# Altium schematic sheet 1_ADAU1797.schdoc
size 848 x 601 mm; Symbol: Drawing-Symbol_A4; Device: Drawing-Symbol_A4; @Project Name: Slowpoke; @Page Count: 7; @Update Date: 2025-12-15; @Create Date: 2025-12-13; @Schematic Name: Slowpoke_Sch; @Page No: 1; @Page Name: ADAU1797; Company: Analog Devices, Inc.; Version: V1.0; Page Size: A0; Drawn: Bruce Tsao; @Create Time: 14:28:29; @Update Time: 16:38:32; Width: 3304; Height: 2338; Region Start: 1; X Region Count: 6; Y Region Count: 4; Blade Width: 10; Title Block Position: 3; @Board Name: Slowpoke
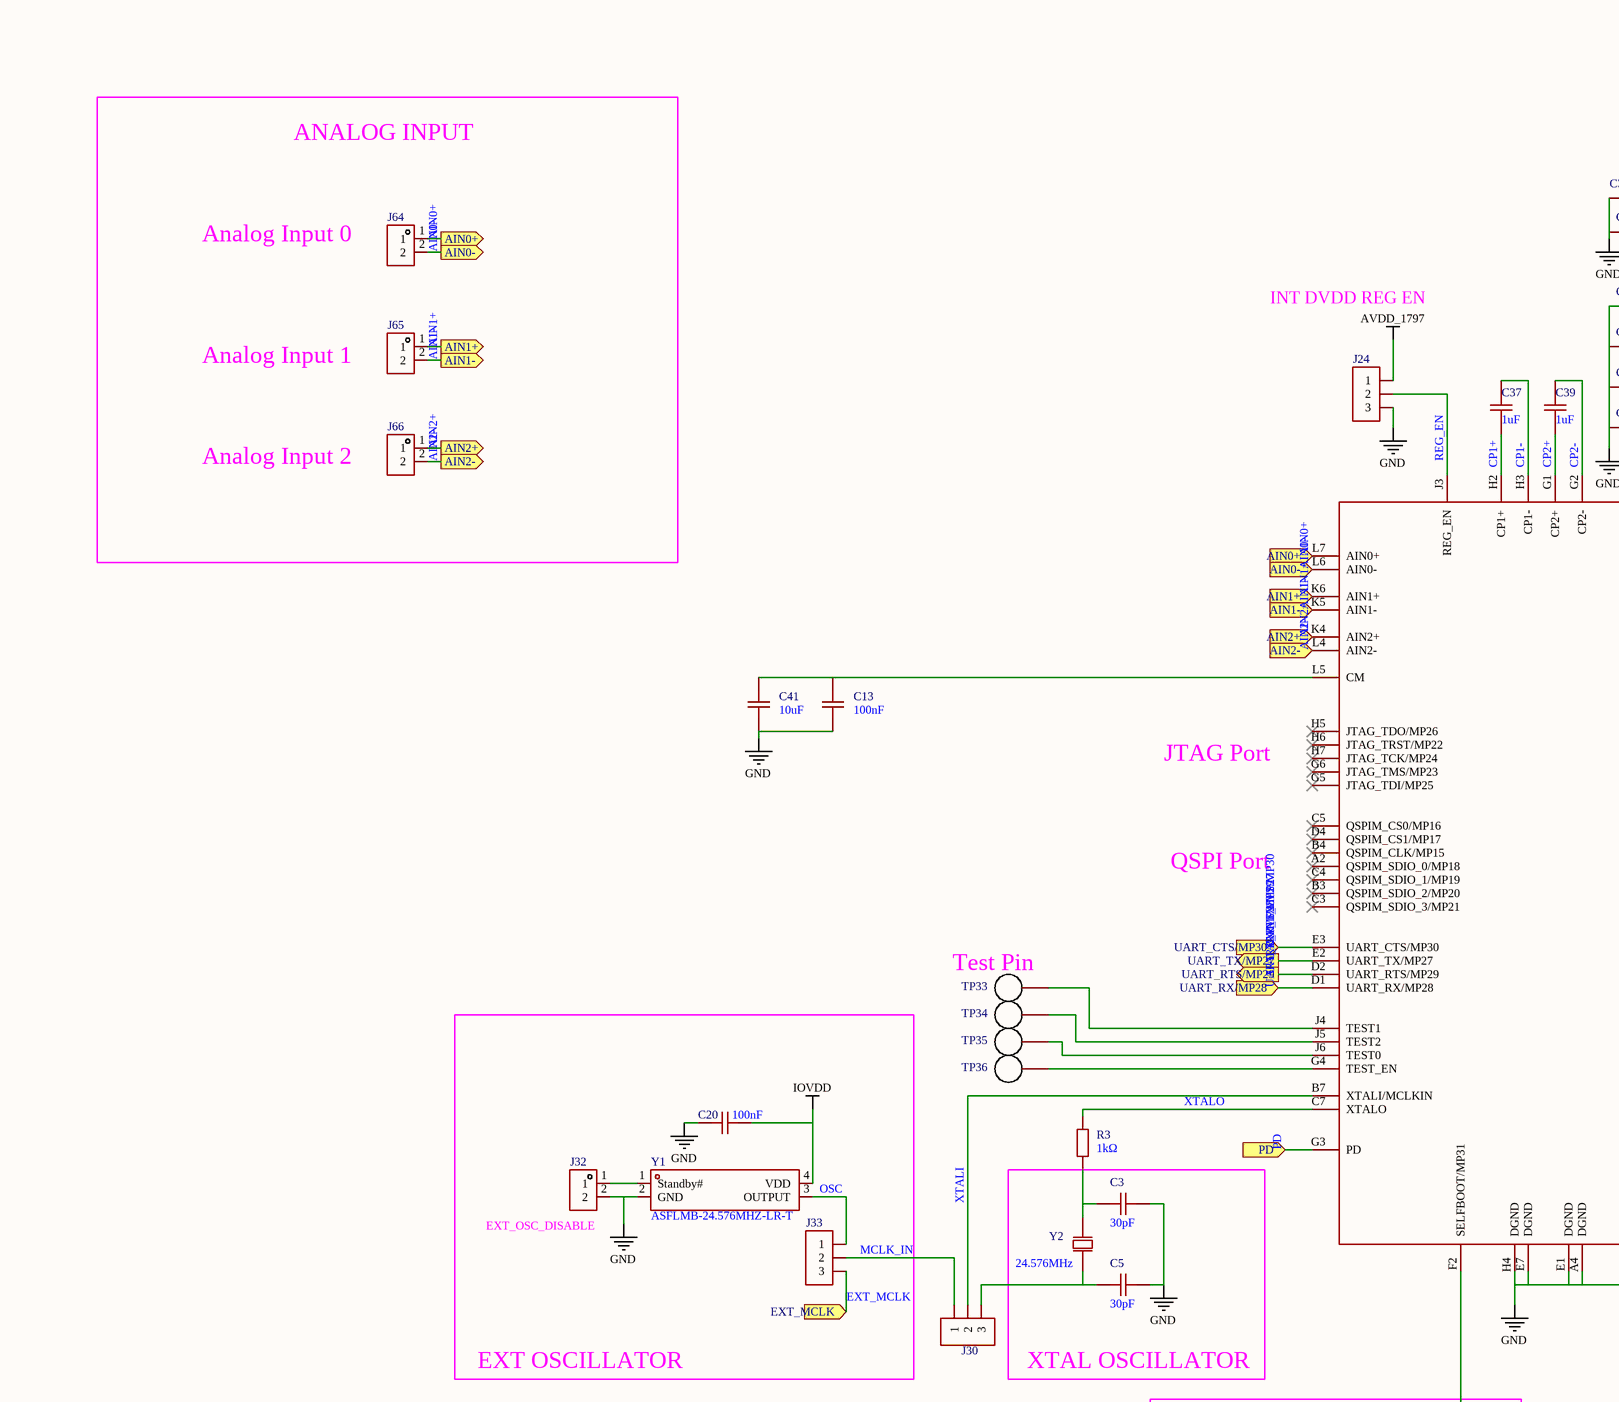
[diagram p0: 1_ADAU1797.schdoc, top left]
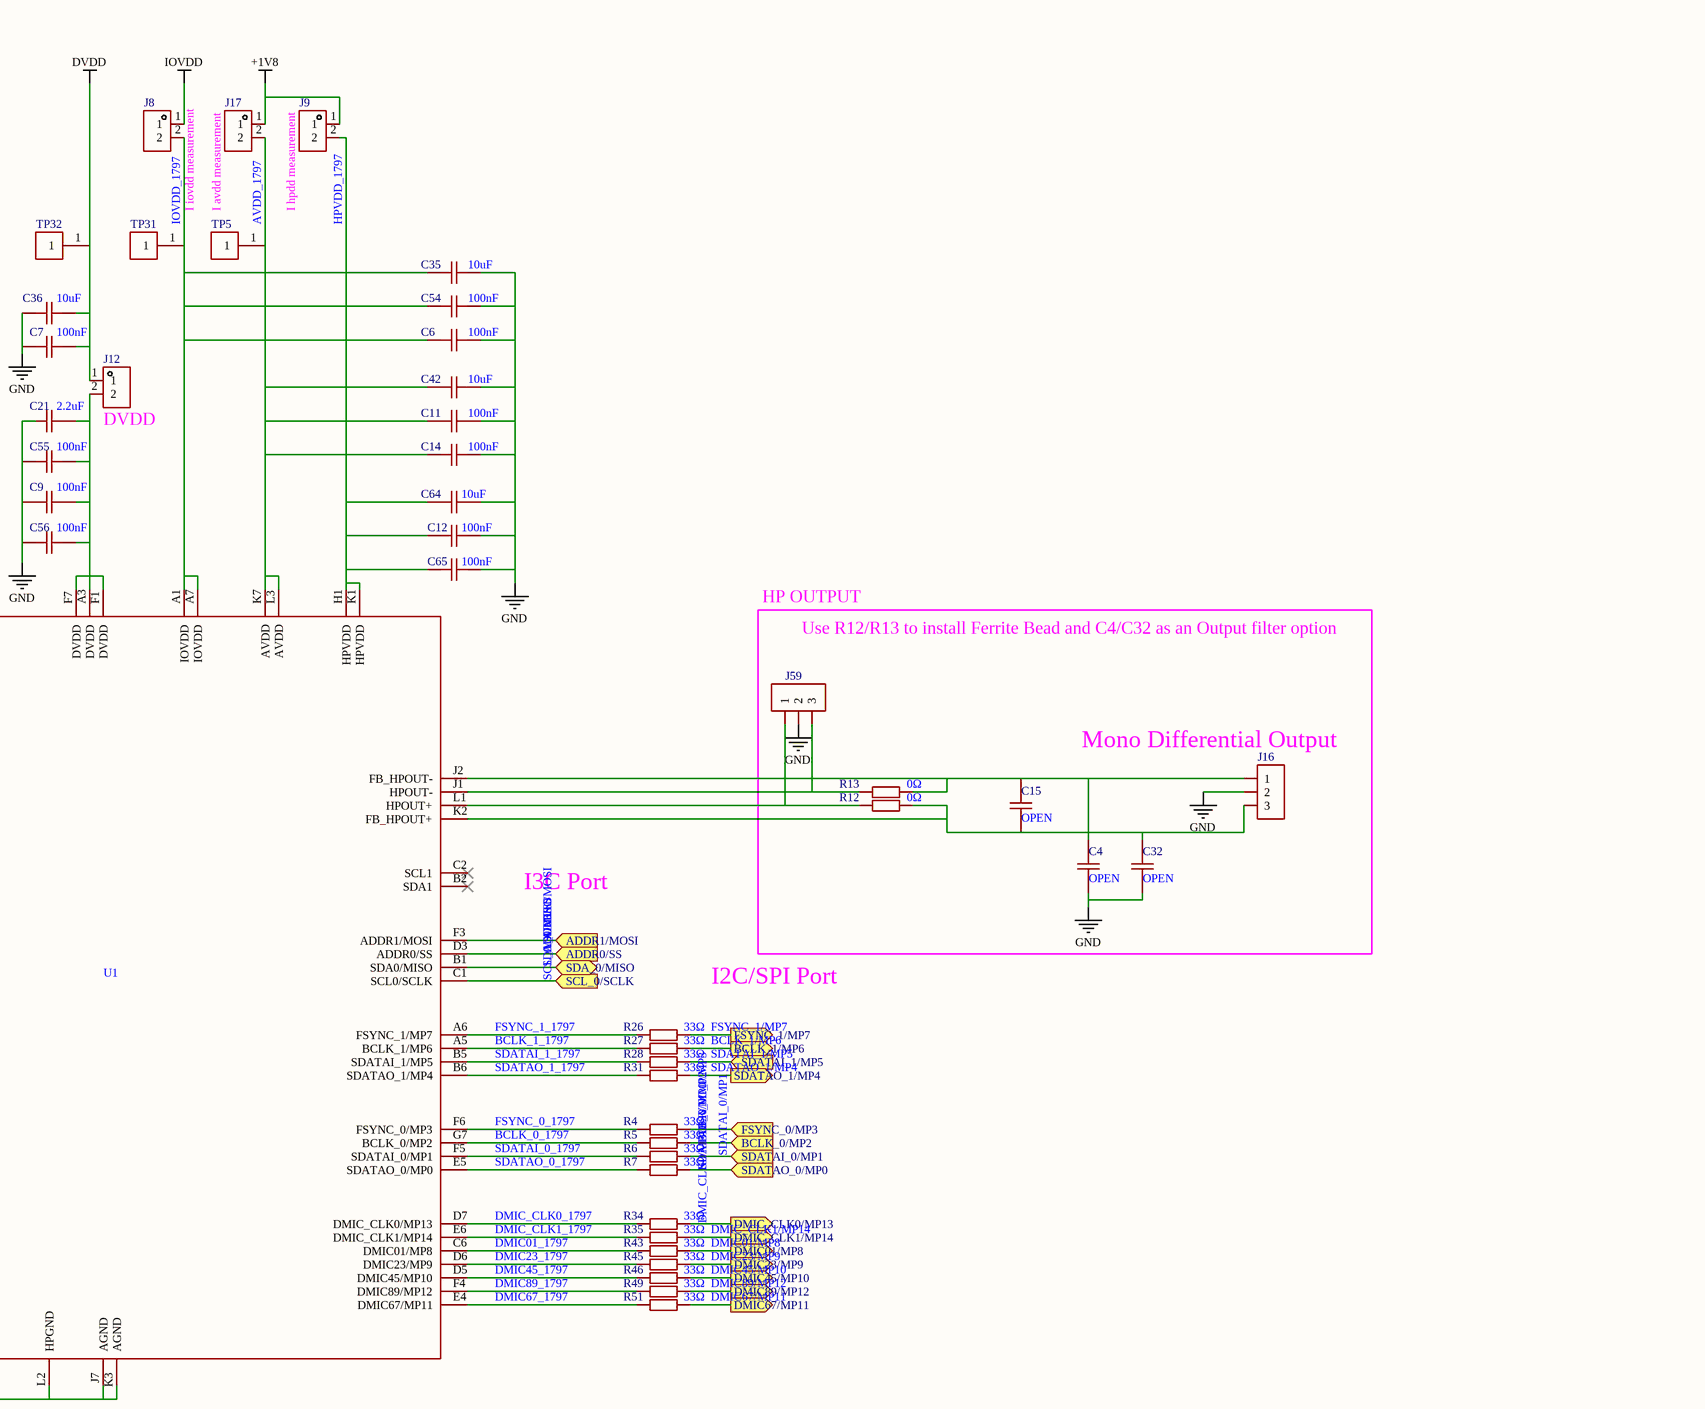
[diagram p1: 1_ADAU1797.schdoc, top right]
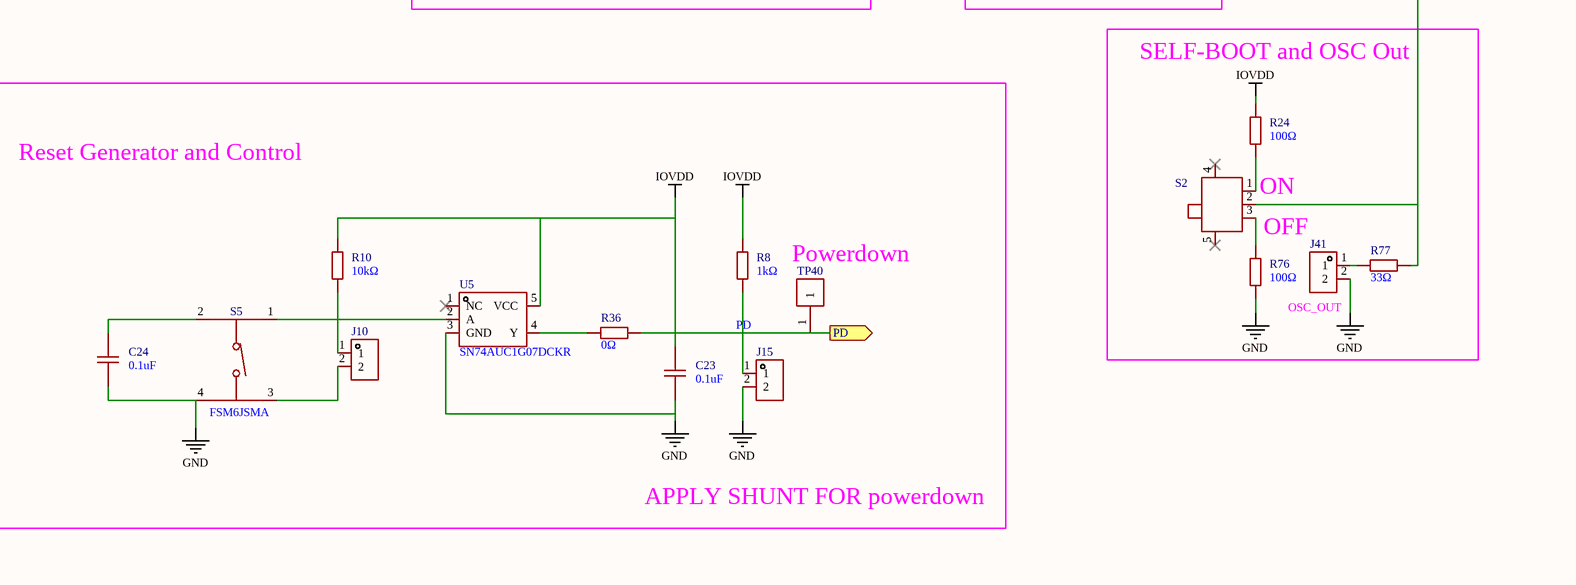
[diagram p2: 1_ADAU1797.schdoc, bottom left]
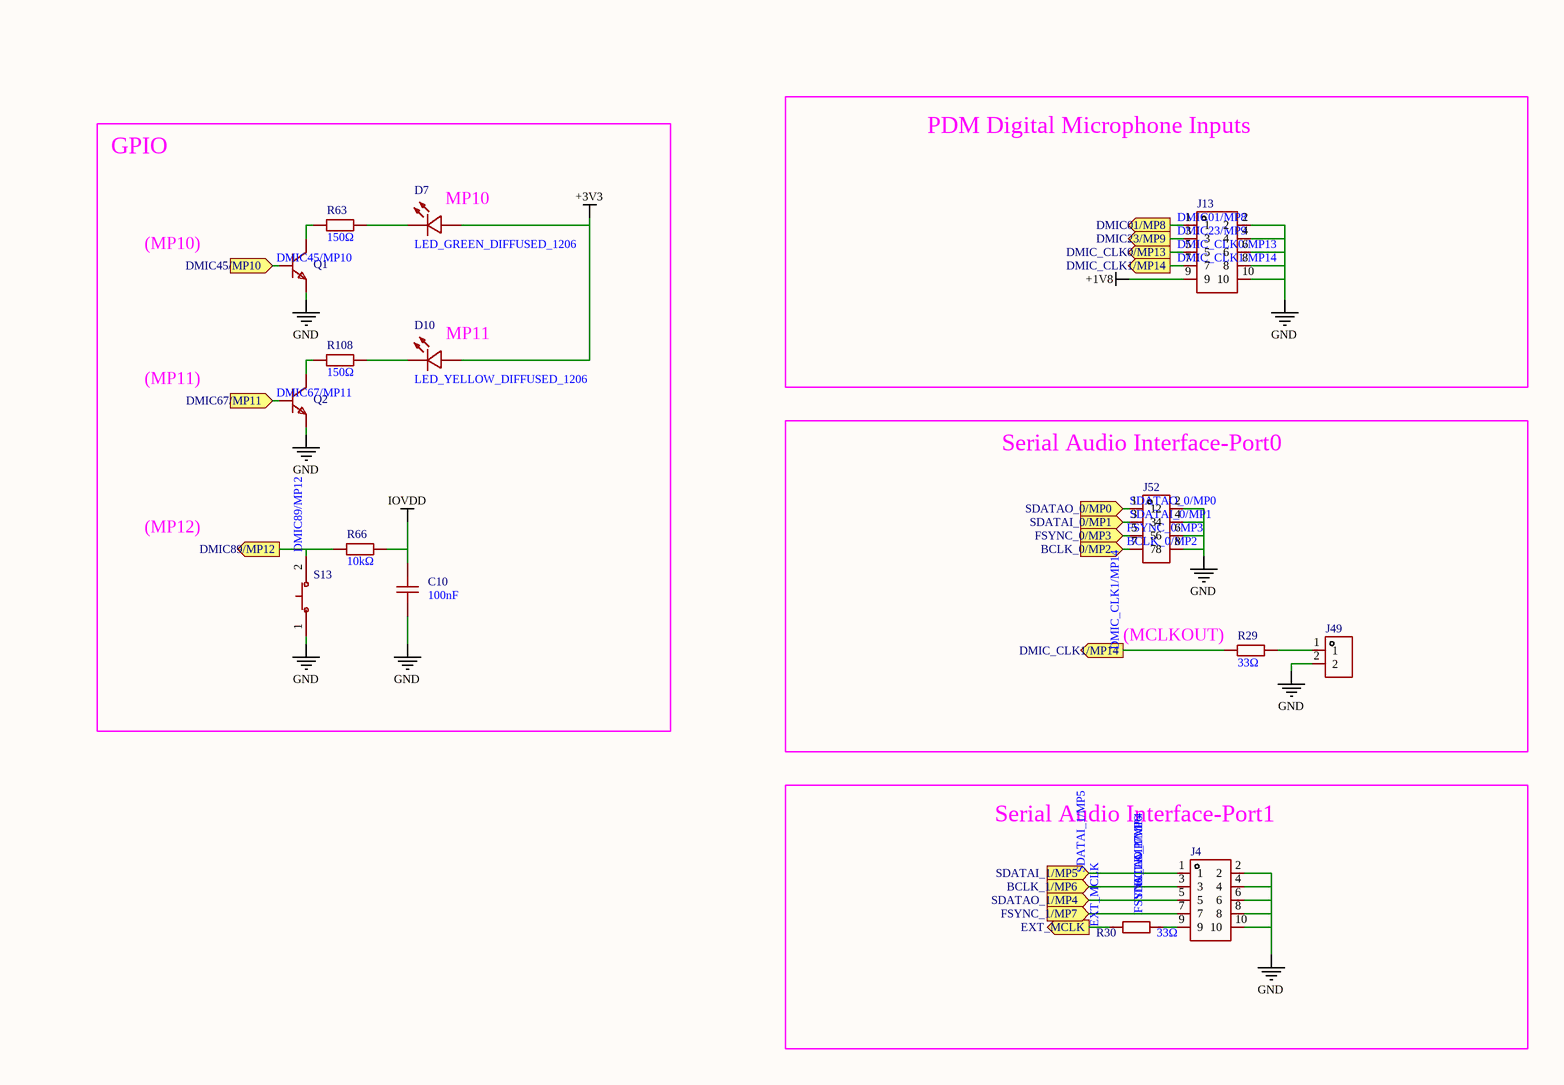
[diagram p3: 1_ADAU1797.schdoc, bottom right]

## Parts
C3  30pF  [C0201]
C4  OPEN  [C0603]
C5  30pF  [C0201]
C6  100nF  [C0402]
C7  100nF  [C0402]
C9  100nF  [C0402]
C10  100nF  [C0402]
C11  100nF  [C0402]
C12  100nF  [C0402]
C13  100nF  [C0402]
C14  100nF  [C0402]
C15  OPEN  [C0603]
C20  100nF  [C0402]
C21  2.2uF  [C0402]
C23  0.1uF  [C0402]
C24  0.1uF  [C0402]
C32  OPEN  [C0603]
C35  10uF  [C0402]
C36  10uF  [C0402]
C37  1uF  [C0402]
C39  1uF  [C0402]
C41  10uF  [C0402]
C42  10uF  [C0402]
C54  100nF  [C0402]
C55  100nF  [C0402]
C56  100nF  [C0402]
C64  10uF  [C0402]
C65  100nF  [C0402]
D7  LED_GREEN_DIFFUSED_1206  [LED1206-RD]
D10  LED_YELLOW_DIFFUSED_1206  [LED1206-RD]
J4  PZ254V-12-10P  [HDR-TH_10P-P2.54-V-M-R2-C5-S2.54]  (value not drawn)
J8  PZ254V-11-02P  [HDR-TH_2P-P2.54-V-M]  (value not drawn)
J9  PZ254V-11-02P  [HDR-TH_2P-P2.54-V-M]  (value not drawn)
J10  PZ254V-11-02P  [HDR-TH_2P-P2.54-V-M]  (value not drawn)
J12  PZ254V-11-02P  [HDR-TH_2P-P2.54-V-M]  (value not drawn)
J13  PZ254V-12-10P  [HDR-TH_10P-P2.54-V-M-R2-C5-S2.54]  (value not drawn)
J15  PZ254V-11-02P  [HDR-TH_2P-P2.54-V-M]  (value not drawn)
J16  2.54-1*3P针  [HDR-TH_3P-P2.54-V-M-1]  (value not drawn)
J17  PZ254V-11-02P  [HDR-TH_2P-P2.54-V-M]  (value not drawn)
J24  2.54-1*3P针  [HDR-TH_3P-P2.54-V-M-1]  (value not drawn)
J30  2.54-1*3P针  [HDR-TH_3P-P2.54-V-M-1]  (value not drawn)
J32  PZ254V-11-02P  [HDR-TH_2P-P2.54-V-M]  (value not drawn)
J33  2.54-1*3P针  [HDR-TH_3P-P2.54-V-M-1]  (value not drawn)
J41  PZ254V-11-02P  [HDR-TH_2P-P2.54-V-M]  (value not drawn)
J49  PZ254V-11-02P  [HDR-TH_2P-P2.54-V-M]  (value not drawn)
J52  PZ254V-12-8P  [HDR-TH_8P-P2.54-V-M-R2-C4-S2.54]  (value not drawn)
J59  2.54-1*3P针  [HDR-TH_3P-P2.54-V-M-1]  (value not drawn)
J64  PZ254V-11-02P  [HDR-TH_2P-P2.54-V-M]  (value not drawn)
J65  PZ254V-11-02P  [HDR-TH_2P-P2.54-V-M]  (value not drawn)
J66  PZ254V-11-02P  [HDR-TH_2P-P2.54-V-M]  (value not drawn)
Q1  DTC114YET1G  [SC-75-3_L1.6-W0.8-P1.00-LS1.7-BR]  (value not drawn)
Q2  DTC114YET1G  [SC-75-3_L1.6-W0.8-P1.00-LS1.7-BR]  (value not drawn)
R3  1kΩ  [R0201]
R4  33Ω  [R0201]
R5  33Ω  [R0201]
R6  33Ω  [R0201]
R7  33Ω  [R0201]
R8  1kΩ  [R0201]
R10  10kΩ  [R0201]
R12  0Ω  [R0603]
R13  0Ω  [R0603]
R24  100Ω  [R0201]
R26  33Ω  [R0201]
R27  33Ω  [R0201]
R28  33Ω  [R0201]
R29  33Ω  [R0201]
R30  33Ω  [R0201]
R31  33Ω  [R0201]
R34  33Ω  [R0201]
R35  33Ω  [R0201]
R36  0Ω  [R0402]
R43  33Ω  [R0201]
R45  33Ω  [R0201]
R46  33Ω  [R0201]
R49  33Ω  [R0201]
R51  33Ω  [R0201]
R63  150Ω  [R0805]
R66  10kΩ  [R0201]
R76  100Ω  [R0201]
R77  33Ω  [R0201]
R108  150Ω  [R0805]
S2  SS12D07VG4 087  [SW-TH_SS12D07VG4]  (value not drawn)
S5  FSM6JSMA  [SW-SMD_4P-L6.0-W6.0-P4.50-LS10.0-BL]
S13  TS3643TP  [KEY-SMD_L6.0-W3.5-LS8.4]  (value not drawn)
TP5  RH-5000  [TEST-TH_BD2.54-P1.4_RED]  (value not drawn)
TP31  RH-5000  [TEST-TH_BD2.54-P1.4_RED]  (value not drawn)
TP32  RH-5000  [TEST-TH_BD2.54-P1.4_RED]  (value not drawn)
TP33  RH-5002  [TESTPOINT-TH_BD2.5-D1.2_RH-5002]  (value not drawn)
TP34  RH-5002  [TESTPOINT-TH_BD2.5-D1.2_RH-5002]  (value not drawn)
TP35  RH-5002  [TESTPOINT-TH_BD2.5-D1.2_RH-5002]  (value not drawn)
TP36  RH-5002  [TESTPOINT-TH_BD2.5-D1.2_RH-5002]  (value not drawn)
TP40  RH-5000  [TEST-TH_BD2.54-P1.4_RED]  (value not drawn)
U1  (no value)  [ADAU1797_WLCSP_CB-77-1]
U5  SN74AUC1G07DCKR  [SC-70-5_L2.0-W1.3-P0.65-LS2.1-BR]
Y1  ASFLMB-24.576MHZ-LR-T  [OSC-SMD_4P-L5.0-W3.2-BL_ASFLMB]
Y2  24.576MHz  [HC-49US_L11.5-W4.5-P4.88]

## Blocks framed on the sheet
Mono Differential Output: C4 C15 C32 J16 J59 R12 R13
EXT OSCILLATOR: C20 J32 J33 Y1
XTAL OSCILLATOR: C3 C5 Y2
GPIO: C10 D7 D10 Q1 Q2 R63 R66 R108 S13
PDM Digital Microphone Inputs: J13
Serial Audio Interface-Port0: J49 J52 R29
Serial Audio Interface-Port1: J4 R30

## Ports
ADDR0/SS (in), ADDR1/MOSI (in), AIN0+ (in), AIN0+ (out), AIN0- (in), AIN0- (out), AIN1+ (in), AIN1+ (out), AIN1- (in), AIN1- (out), AIN2+ (in), AIN2+ (out), AIN2- (in), AIN2- (out), BCLK_0/MP2 (in), BCLK_1/MP6 (in), BCLK_1/MP6 (out), DMIC01/MP8 (out), DMIC23/MP9 (out), DMIC45/MP10 (in), DMIC45/MP10 (out), DMIC67/MP11 (in), DMIC67/MP11 (out), DMIC89/MP12 (out), DMIC_CLK0/MP13 (out), DMIC_CLK1/MP14 (out), EXT_MCLK (in), EXT_MCLK (out), FSYNC_0/MP3 (in), FSYNC_1/MP7 (in), FSYNC_1/MP7 (out), PD (in), PD (out), SCL_0/SCLK (in), SDA_0/MISO (bidir), SDATAI_0/MP1 (in), SDATAI_1/MP5 (in), SDATAO_0/MP0 (in), SDATAO_1/MP4 (in), SDATAO_1/MP4 (out), UART_CTS/MP30 (in), UART_RTS/MP29 (out), UART_RX/MP28 (in), UART_TX/MP27 (out)

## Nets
+1V8: J9.1 J13.9 J17.1
+3V3: D7.2(A) D10.2(A)
AVDD_1797: C11.2 C14.2 C42.2 J17.2 J24.1 TP5.1 U1.K7(AVDD) U1.L3(AVDD)
DVDD: C7.1 C36.1 J12.1 TP32.1
GND: C3.1 C4.1 C5.1 C6.1 C7.2 C9.2 C10.2 C11.1 C12.1 C13.2 C14.1 C20.2 C21.2 C23.2 C24.1 C32.1 C35.1 C36.2 C41.2 C42.1 C54.1 C55.2 C56.2 C64.1 C65.1 J4.2 J4.4 J4.6 J4.8 J4.10 J13.2 J13.4 J13.6 J13.8 J13.10 J15.2 J16.2 J24.3 J32.2 J41.2 J49.2 J52.2 J52.4 J52.6 J52.8 J59.2 Q1.2(E) Q2.2(E) R76.1 S5.4 S13.1 U1.A4(DGND) U1.E1(DGND) U1.E7(DGND) U1.H4(DGND) U1.J7(AGND) U1.K3(AGND) U1.L2(HPGND) U5.3(GND) Y1.2(GND)
IOVDD: C10.1 C20.1 C23.1 J8.1 R8.2 R10.2 R24.2 R66.1 U5.5(VCC) Y1.4(VDD)
ADDR0/SS: U1.D3(ADDR0/SS) ; port ADDR0/SS
ADDR1/MOSI: U1.F3(ADDR1/MOSI) ; port ADDR1/MOSI
AIN0+: J64.1 U1.L7(AIN0+) ; port AIN0+
AIN0-: J64.2 U1.L6(AIN0-) ; port AIN0-
AIN1+: J65.1 U1.K6(AIN1+) ; port AIN1+
AIN1-: J65.2 U1.K5(AIN1-) ; port AIN1-
AIN2+: J66.1 U1.K4(AIN2+) ; port AIN2+
AIN2-: J66.2 U1.L4(AIN2-) ; port AIN2-
BCLK_0/MP2: J52.7 R5.2 ; port BCLK_0/MP2
BCLK_0_1797: R5.1 U1.G7(BCLK_0/MP2)
BCLK_1/MP6: J4.3 R27.2 ; port BCLK_1/MP6
BCLK_1_1797: R27.1 U1.A5(BCLK_1/MP6)
CP1+: C37.1 U1.H2(CP1+)
CP1-: C37.2 U1.H3(CP1-)
CP2+: C39.1 U1.G1(CP2+)
CP2-: C39.2 U1.G2(CP2-)
DMIC01/MP8: J13.1 R43.2 ; port DMIC01/MP8
DMIC01_1797: R43.1 U1.C6(DMIC01/MP8)
DMIC23/MP9: J13.3 R45.2 ; port DMIC23/MP9
DMIC23_1797: R45.1 U1.D6(DMIC23/MP9)
DMIC45/MP10: Q1.1(B) R46.2 ; port DMIC45/MP10
DMIC45_1797: R46.1 U1.D5(DMIC45/MP10)
DMIC67/MP11: Q2.1(B) R51.2 ; port DMIC67/MP11
DMIC67_1797: R51.1 U1.E4(DMIC67/MP11)
DMIC89/MP12: R49.2 R66.2 S13.2 ; port DMIC89/MP12
DMIC89_1797: R49.1 U1.F4(DMIC89/MP12)
DMIC_CLK0/MP13: J13.5 R34.2 ; port DMIC_CLK0/MP13
DMIC_CLK0_1797: R34.1 U1.D7(DMIC_CLK0/MP13)
DMIC_CLK1/MP14: J13.7 R29.1 R35.2 ; port DMIC_CLK1/MP14
DMIC_CLK1_1797: R35.1 U1.E6(DMIC_CLK1/MP14)
EXT_MCLK: J33.3 R30.1 ; port EXT_MCLK
FSYNC_0/MP3: J52.5 R4.2 ; port FSYNC_0/MP3
FSYNC_0_1797: R4.1 U1.F6(FSYNC_0/MP3)
FSYNC_1/MP7: J4.7 R26.2 ; port FSYNC_1/MP7
FSYNC_1_1797: R26.1 U1.A6(FSYNC_1/MP7)
HPVDD_1797: C12.2 C64.2 C65.2 J9.2 U1.H1(HPVDD) U1.K1(HPVDD)
IOVDD_1797: C6.2 C35.2 C54.2 J8.2 TP31.1 U1.A1(IOVDD) U1.A7(IOVDD)
MCLK_IN: J30.1 J33.2
OSC: J33.1 Y1.3(OUTPUT)
PD: J15.1 R8.1 R36.2 TP40.1 U1.G3(PD) ; port PD
REG_EN: J24.2 U1.J3(REG_EN)
SCL_0/SCLK: U1.C1(SCL0/SCLK) ; port SCL_0/SCLK
SDA_0/MISO: U1.B1(SDA0/MISO) ; port SDA_0/MISO
SDATAI_0/MP1: J52.3 R6.2 ; port SDATAI_0/MP1
SDATAI_0_1797: R6.1 U1.F5(SDATAI_0/MP1)
SDATAI_1/MP5: J4.1 R28.2 ; port SDATAI_1/MP5
SDATAI_1_1797: R28.1 U1.B5(SDATAI_1/MP5)
SDATAO_0/MP0: J52.1 R7.2 ; port SDATAO_0/MP0
SDATAO_0_1797: R7.1 U1.E5(SDATAO_0/MP0)
SDATAO_1/MP4: J4.5 R31.2 ; port SDATAO_1/MP4
SDATAO_1_1797: R31.1 U1.B6(SDATAO_1/MP4)
UART_CTS/MP30: U1.E3(UART_CTS/MP30) ; port UART_CTS/MP30
UART_RTS/MP29: U1.D2(UART_RTS/MP29) ; port UART_RTS/MP29
UART_RX/MP28: U1.D1(UART_RX/MP28) ; port UART_RX/MP28
UART_TX/MP27: U1.E2(UART_TX/MP27) ; port UART_TX/MP27
XTALI: J30.2 U1.B7(XTALI/MCLKIN)
XTALO: R3.2 U1.C7(XTALO)
NetC3_2: C3.2 R3.1 Y2.2(OSC2)
NetC4_2: C4.2 C15.2 J16.1 R13.2 U1.J2(FB_HPOUT-)
NetC5_2: C5.2 J30.3 Y2.1(OSC1)
NetC9_1: C9.1 C21.1 C55.1 C56.1 J12.2 U1.A3(DVDD) U1.F1(DVDD) U1.F7(DVDD)
NetC13_1: C13.1 C41.1 U1.L5(CM)
NetC15_1: C15.1 C32.2 J16.3 R12.2 U1.K2(FB_HPOUT+)
NetC24_2: C24.2 S5.2
NetD7_1: D7.1(K) R63.1
NetD10_1: D10.1(K) R108.1
NetJ4_9: J4.9 R30.2
NetJ10_1: J10.1 R10.1 S5.1 U5.2(A)
NetJ10_2: J10.2 S5.3
NetJ32_1: J32.1 Y1.1(Standby#)
NetJ41_1: J41.1 R77.1
NetJ49_1: J49.1 R29.2
NetJ59_1: J59.1 R12.1 U1.L1(HPOUT+)
NetJ59_3: J59.3 R13.1 U1.J1(HPOUT-)
NetQ1_3: Q1.3(C) R63.2
NetQ2_3: Q2.3(C) R108.2
NetR24_1: R24.1 S2.1
NetR36_1: R36.1 U5.4(Y)
NetR76_2: R76.2 S2.3
NetR77_2: R77.2 S2.2 U1.F2(SELFBOOT/MP31)
NetTP33_1: TP33.1 U1.J4(TEST1)
NetTP34_1: TP34.1 U1.J5(TEST2)
NetTP35_1: TP35.1 U1.J6(TEST0)
NetTP36_1: TP36.1 U1.G4(TEST_EN)

Not connected (* = marked no-connect by the designer): S2 4* 5*; U1 A2(QSPIM_SDIO_0/MP18)* B2(SDA1)* B3(QSPIM_SDIO_2/MP20)* B4(QSPIM_CLK/MP15)* C2(SCL1)* C3(QSPIM_SDIO_3/MP21)* C4(QSPIM_SDIO_1/MP19)* C5(QSPIM_CS0/MP16)* D4(QSPIM_CS1/MP17)* G5(JTAG_TDI/MP25)* G6(JTAG_TMS/MP23)* H5(JTAG_TDO/MP26)* H6(JTAG_TRST/MP22)* H7(JTAG_TCK/MP24)*; U5 1(NC)*

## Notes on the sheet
- (near J8) I iovdd measurement
- I avdd measurement
- I hpdd measurement
- ANALOG INPUT
- Analog Input 0
- INT DVDD REG EN
- (near J12) DVDD
- Analog Input 1
- Analog Input 2
- HP OUTPUT
- Use R12/R13 to install Ferrite Bead and C4/C32 as an Output filter option
- JTAG Port
- I3C Port
- QSPI Port
- I2C/SPI Port
- (near TP33) Test Pin
- (near J32) EXT_OSC_DISABLE
- SELF-BOOT and OSC Out
- Reset Generator and Control
- (MP10)
- (near D7) MP10
- ON
- OFF
- Powerdown
- (MP11)
- (near D10) MP11
- (near J41) OSC_OUT
- (MP12)
- APPLY SHUNT FOR powerdown
- (near R29) (MCLKOUT)

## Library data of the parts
C3 C5 = GRM0335C1H300GA01D: Manufacturer: muRata(村田); Add into BOM: yes; Tolerance: ±2%
C4 C15 C32 = CGA0603X5R105K500JT: Manufacturer: HRE(芯声); Symbol: 0402X7R104K500NT; Add into BOM: yes; Tolerance: ±10%; Voltage Rating: 50V; Temperature Coefficient: X5R
C6 C7 C9-C14 C20 C21 C35 C36 C41 C42 C54-C56 C64 C65 = FCC0402B104K160AT: Manufacturer: FOJAN(富捷); Symbol: C1005X5R225MCT; Add into BOM: yes; Tolerance: ±10%; Voltage Rating: 16V; Temperature Coefficient: X7R
C23 C24 = GRM155R71C104KA88D: Manufacturer: muRata(村田); Add into BOM: yes; Tolerance: ±10%; Voltage Rating: 16V; Temperature Coefficient: X7R
C37 C39 = 0402X7R104K500NT: Manufacturer: AIDE(爱迪电容); Add into BOM: yes; Tolerance: ±10%; Voltage Rating: 50V; Temperature Coefficient: X7R
D7 D10 = LTST-C150KRKT: Manufacturer: LITEON(光宝); Add into BOM: yes; Emitted Color: Red; Forward Voltage (VF): 2V; Power Dissipation: 62.5mW; Forward Current: 20mA; Dominant Wavelength: 624nm; Peak Wavelength: 639nm; Lens Color: 无色透明透镜; Luminous Intensity: 54mcd; Viewing Angle: 130°
J4 J13 = PZ254V-12-10P: Manufacturer: XFCN(兴飞); Add into BOM: yes; Pin Structure: 2x5P; Pitch: 2.54mm; Circluar Pins/Square Pins: Pin Header
J8-J10 J12 J15 J17 J32 J41 J49 J64-J66 = PZ254V-11-02P: Manufacturer: XFCN(兴飞); Add into BOM: yes; Pin Structure: 1x2P; Pitch: 2.54mm; Circluar Pins/Square Pins: Pin Header
J16 J24 J30 J33 J59 = 2.54-1*3P针: Manufacturer: BOOMELE(博穆精密); Symbol: Header-Male-2.54_1x3; Add into BOM: yes; Pin Structure: 1x3P; Pitch: 2.54mm; Circluar Pins/Square Pins: Pin Header; Current Rating: 3A
J52 = PZ254V-12-8P: Manufacturer: XFCN(兴飞); Add into BOM: yes; Pin Structure: 2x4P; Pitch: 2.54mm; Circluar Pins/Square Pins: Pin Header
Q1 Q2 = DTC114YET1G: Manufacturer: onsemi(安森美); Add into BOM: yes; Collector - Emitter Voltage VCEO: 50V; Current - Collector(Ic): 100mA; Pd - Power Dissipation: 200mW; DC Current Gain: 80@5.0mA,10V; Input Voltage (VI(on)@Ic,Vce): 1.4V@1.0mA,0.3V; Voltage - Input(Max)(VI(off)): 500mV@100uA,5.0V; Output Voltage(VO(on)): 200mV; Input Resistor: 10kΩ; Resistor Ratio: 0.21
R3 R8 R10 R66 = 0201WMF1001TEE: Manufacturer: UNI-ROYAL(厚声); Add into BOM: yes; Tolerance: ±1%; Power(Watts): 50mW; Voltage-Supply(Max): 25V; Temperature Coefficient: ±200ppm/℃
R4-R7 R24 R26-R31 R34 R35 R43 R45 R46 R49 R51 R76 R77 = 0201WMJ0330TEE: Manufacturer: UNI-ROYAL(厚声); Add into BOM: yes; Tolerance: ±5%; Power(Watts): 50mW; Voltage-Supply(Max): 25V; Temperature Coefficient: ±200ppm/℃
R12 R13 = 0603WAF0000T5E: Manufacturer: UNI-ROYAL(厚声); Add into BOM: yes; Tolerance: ±1%; Power(Watts): 100mW; Voltage-Supply(Max): 75V
R36 = 0402WGF0000TCE: Manufacturer: UNI-ROYAL(厚声); Add into BOM: yes; Tolerance: ±1%; Power(Watts): 62.5mW; Voltage-Supply(Max): 50V; Temperature Coefficient: ±800ppm/℃
R63 R108 = 0805W8F1002T5E: Manufacturer: UNI-ROYAL(厚声); Add into BOM: yes; Tolerance: ±1%; Power(Watts): 125mW; Voltage-Supply(Max): 150V; Temperature Coefficient: ±100ppm/℃
S2 = SS12D07VG4 087: Manufacturer: SHOU HAN(首韩); Add into BOM: yes; Circuit: SPDT; Switch Height: 4.7mm; Current Rating: 500mA; Voltage Rating: 50V; Life: 5000 Cycles
S5 = FSM6JSMA: Manufacturer: TE Connectivity(泰科电子); Add into BOM: yes; Circuit: SPST; Actuator Style: Round Button; Operating Force: 1.6N; Switch Height: 7mm; Contact Current: 50mA; Voltage Rating: 24V
S13 = TS3643TP: Manufacturer: SHOU HAN(首韩); Add into BOM: yes; Circuit: SPST; Actuator Style: Rectangular Button; Operating Force: 2.6N; Contact Current: 50mA; Voltage Rating: 12V
TP5 TP31 TP32 TP40 = RH-5000: Manufacturer: 荣和; Add into BOM: yes; Connector Type: Pin Type (Through-Board); Plastic Color: Red; Board Space (Diameter φ/ Length x Width): 2.5mm
TP33-TP36 = RH-5002: Manufacturer: 荣和; Add into BOM: yes; Connector Type: Pin Type (Through-Board); Plastic Color: White; Board Space (Diameter φ/ Length x Width): 2.5mm
U1 = ADAU1797: Add into BOM: yes
U5 = SN74AUC1G07DCKR: Manufacturer: TI(德州仪器); Add into BOM: yes; output type: Open Drain; Voltage - Supply: 0.8V~2.7V; Number of Elements: 1; Current - Output Low(IOL): 9mA; Logic Family: 74AUC
Y1 = ASFLMB-24.576MHZ-LR-T: Manufacturer: ABRACON; Add into BOM: yes; Frequency Stability: ±25ppm; Voltage - Supply: 1.8V~3.3V
Y2 = H1OEL89CSC-SUGYLC-24.576M: Manufacturer: YXC(扬兴晶振); Add into BOM: yes; Normal temperature Frequency Tolerance: ±20ppm; Load Capacitance: 20pF; Frequency Stability: ±30ppm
